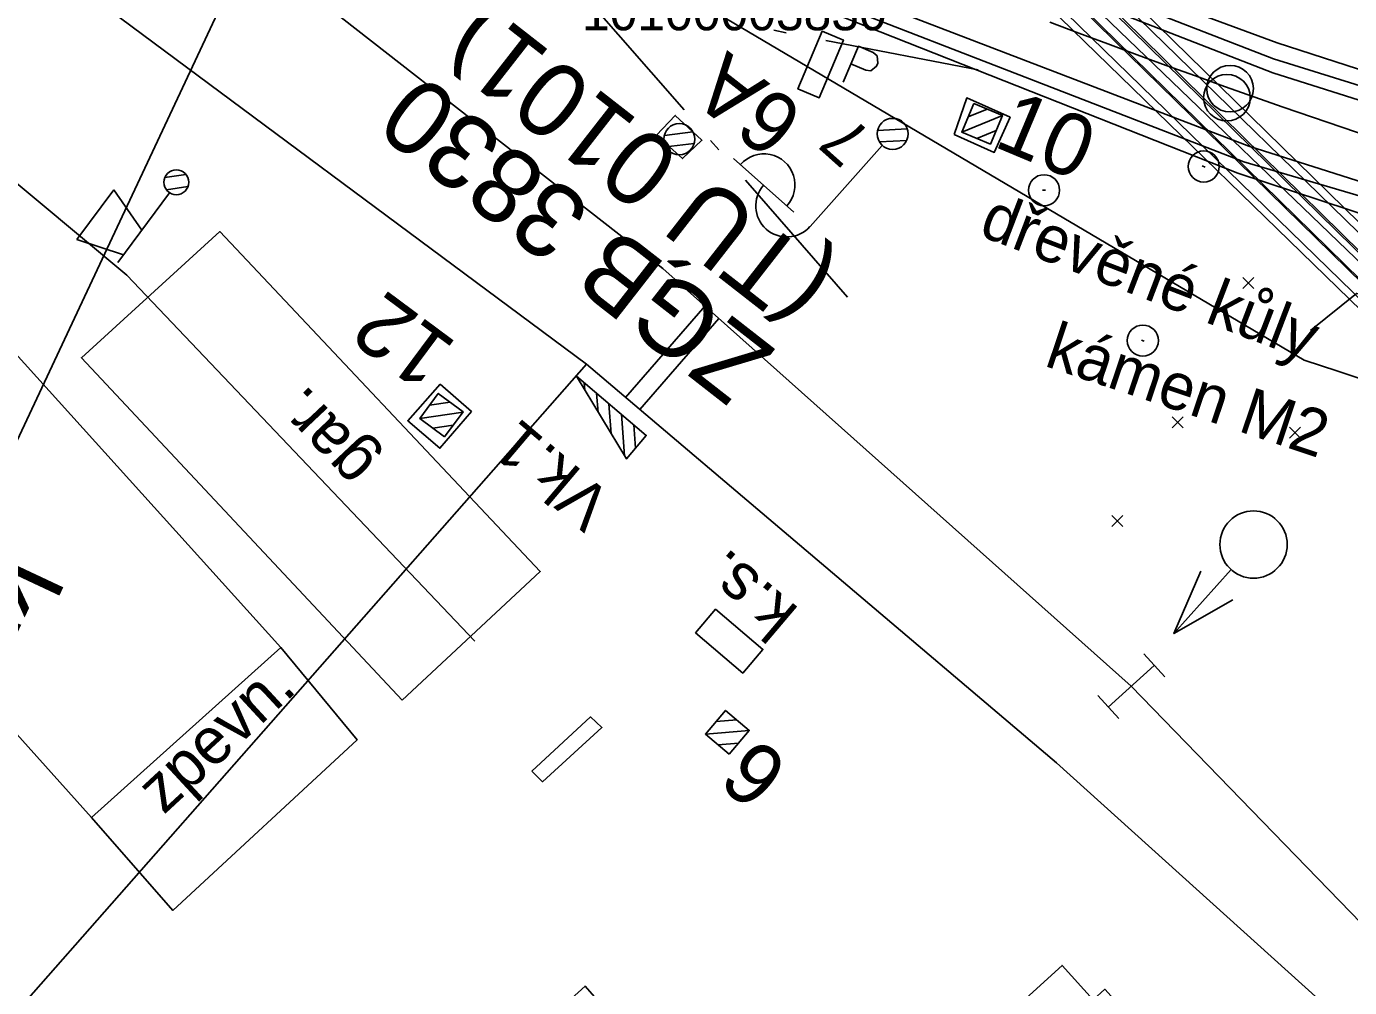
# Model space of a CAD drawing. Extents: x -800194 to -799078, y -1007177 to -1006597.
# Drawn here: x -799787.92 to -799745.3, y -1007007.87 to -1006976.93 of the extents above; entities that cross this region are included whole.
import ezdxf

# ---------------------------------------------------------------- set-up
doc = ezdxf.new("R2010")
doc.units = 0
for name, color, linetype in [('02_Osa_koleje', 7, 'Continuous'), ('_návrh', 7, 'Continuous'), ('_Vrstva 7 - Přesunutá', 7, 'Continuous'), ('Vrstva 1', 7, 'Continuous'), ('Vrstva 11', 7, 'Continuous'), ('Vrstva 12', 7, 'Continuous'), ('Vrstva 16', 7, 'Continuous'), ('Vrstva 17', 7, 'Continuous'), ('Vrstva 18', 7, 'Continuous'), ('Vrstva 23', 7, 'Continuous'), ('Vrstva 25', 7, 'Continuous'), ('Vrstva 3', 7, 'Continuous'), ('Vrstva 33', 7, 'Continuous'), ('Vrstva 36', 7, 'Continuous'), ('Vrstva 4', 7, 'Continuous'), ('Vrstva 49', 7, 'Continuous'), ('Vrstva 5', 7, 'Continuous'), ('Vrstva 50', 7, 'Continuous'), ('Vrstva 55', 7, 'Continuous'), ('Vrstva 60', 7, 'Continuous'), ('Vrstva 63', 7, 'Continuous'), ('Vrstva 7', 7, 'Continuous')]:
    doc.layers.add(name, color=color, linetype=linetype)

msp = doc.modelspace()

# ---------------------------------------------------------------- linework, layer by layer
at = {"layer": '02_Osa_koleje'}
msp.add_lwpolyline([(-799754.96, -1006976.789), (-799754.025, -1006977.142), (-799753.088, -1006977.491), (-799752.149, -1006977.838), (-799751.21, -1006978.181), (-799750.27, -1006978.521), (-799749.328, -1006978.858), (-799748.386, -1006979.192), (-799747.442, -1006979.523), (-799746.497, -1006979.85), (-799745.551, -1006980.175), (-799744.604, -1006980.496)], dxfattribs=at)
at = {"layer": '_návrh'}
for points in [[(-799821.595, -1006948.007), (-799811.064, -1006954.324), (-799803.753, -1006958.707), (-799793.935, -1006964.581), (-799784.224, -1006971.671), (-799782.913, -1006972.63), (-799767.418, -1006984.719), (-799752.333, -1006998.173), (-799735.027, -1007015.997), (-799721.623, -1007030.81), (-799713.555, -1007039.726), (-799713.111, -1007040.218)], [(-799820.755, -1006954.001), (-799803.004, -1006964.743), (-799786.682, -1006975.322), (-799769.882, -1006987.807), (-799754.745, -1007000.643), (-799736.311, -1007017.261), (-799721.623, -1007030.81)]]:
    msp.add_lwpolyline(points, dxfattribs=at)
at = {"layer": '_Vrstva 7 - Přesunutá'}
msp.add_circle((-799749.152, -1006978.93), 0.75, dxfattribs=at)
at = {"layer": 'Vrstva 1'}
msp.add_lwpolyline([(-799773.482, -1006996.72), (-799784.684, -1006984.939), (-799796.383, -1006975.181), (-799798.809, -1006973.435), (-799814.345, -1006963.355), (-799826.008, -1006956.394)], dxfattribs=at)
at = {"layer": 'Vrstva 11'}
for p, q in [((-799757.587, -1006979.838), (-799756.976, -1006979.588)), ((-799757.792, -1006980.327), (-799756.487, -1006979.793)), ((-799766.454, -1006980.322), (-799767.374, -1006980.435)), ((-799757.307, -1006980.534), (-799756.688, -1006980.28)), ((-799766.415, -1006980.695), (-799767.322, -1006980.806)), ((-799774.277, -1006989.026), (-799774.939, -1006989.123)), ((-799773.856, -1006989.342), (-799775.251, -1006989.548)), ((-799774.172, -1006989.768), (-799774.826, -1006989.864)), ((-799765.042, -1006999.255), (-799765.709, -1006999.31)), ((-799764.642, -1006999.598), (-799766.047, -1006999.714)), ((-799764.985, -1007000.003), (-799765.643, -1007000.057))]:
    msp.add_line(p, q, dxfattribs=at)
for points in [[(-799757.407, -1006979.408), (-799756.485, -1006979.794), (-799756.871, -1006980.716), (-799757.793, -1006980.33)], [(-799774.451, -1006990.143), (-799775.254, -1006989.546), (-799774.657, -1006988.743), (-799773.854, -1006989.34)], [(-799765.287, -1007000.359), (-799766.05, -1006999.712), (-799765.403, -1006998.949), (-799764.64, -1006999.596)]]:
    msp.add_lwpolyline(points, close=True, dxfattribs=at)
msp.add_circle((-799766.892, -1006980.556), 0.5, dxfattribs=at)
at = {"layer": 'Vrstva 12'}
for points in [[(-799758.044, -1006980.409), (-799757.635, -1006979.231), (-799756.238, -1006979.849), (-799756.747, -1006980.984), (-799758.044, -1006980.409)], [(-799767.624, -1006980.428), (-799767.025, -1006979.792), (-799766.166, -1006980.593), (-799766.788, -1006981.184), (-799767.624, -1006980.428)], [(-799774.6, -1006988.448), (-799773.586, -1006989.331), (-799774.604, -1006990.51), (-799775.637, -1006989.625), (-799774.6, -1006988.448)]]:
    msp.add_lwpolyline(points, dxfattribs=at)
at = {"layer": 'Vrstva 16'}
for points in [[(-799783.708, -1006948.669), (-799779.9, -1006952.065), (-799777.252, -1006954.333), (-799763.672, -1006965.935), (-799754.476, -1006974.829), (-799742.393, -1006986.703), (-799736.524, -1006991.578), (-799726.778, -1006999.642)], [(-799726.857, -1006999.659), (-799736.574, -1006991.623), (-799742.439, -1006986.725), (-799754.518, -1006974.879), (-799763.734, -1006965.993), (-799777.293, -1006954.374), (-799779.945, -1006952.099), (-799783.722, -1006948.693)], [(-799784.356, -1006949.5), (-799780.347, -1006952.62), (-799777.716, -1006954.827), (-799764.168, -1006966.436), (-799754.935, -1006975.363), (-799742.857, -1006987.188), (-799736.94, -1006992.081), (-799727.324, -1007000.028)], [(-799727.258, -1006999.988), (-799736.887, -1006992.032), (-799742.859, -1006987.132), (-799754.894, -1006975.337), (-799764.135, -1006966.374), (-799777.698, -1006954.783), (-799780.331, -1006952.581), (-799784.321, -1006949.462)], [(-799779.465, -1006951.506), (-799778.251, -1006952.583), (-799776.738, -1006953.884), (-799763.224, -1006965.504), (-799753.999, -1006974.421), (-799741.964, -1006986.204), (-799736.168, -1006991.012), (-799728.577, -1006997.215), (-799726.123, -1006999.163)], [(-799727.952, -1007000.326), (-799729.82, -1006998.717), (-799737.37, -1006992.486), (-799743.358, -1006987.594), (-799755.401, -1006975.883), (-799764.592, -1006966.926), (-799778.073, -1006955.449), (-799779.598, -1006954.142), (-799780.843, -1006953.125)], [(-799785.824, -1007002.398), (-799779.728, -1006996.929), (-799777.27, -1006999.897), (-799783.203, -1007005.389), (-799785.824, -1007002.398)]]:
    msp.add_lwpolyline(points, dxfattribs=at)
at = {"layer": 'Vrstva 17'}
for points in [[(-799746.564, -1006986.717), (-799745.074, -1006985.521), (-799738.458, -1006986.883), (-799728.745, -1006990.03), (-799724.988, -1006990.685)], [(-799776.389, -1007013.671), (-799769.929, -1007007.827), (-799768.722, -1007009.2), (-799767.356, -1007008.223), (-799755.62, -1007020.402)]]:
    msp.add_lwpolyline(points, dxfattribs=at)
at = {"layer": 'Vrstva 18'}
for points in [[(-799776.738, -1006953.884), (-799763.224, -1006965.504), (-799753.999, -1006974.421), (-799741.964, -1006986.204), (-799736.168, -1006991.012)], [(-799728.689, -1006997.417), (-799736.272, -1006991.186), (-799742.111, -1006986.385), (-799754.178, -1006974.631), (-799763.368, -1006965.72), (-799777.061, -1006954.31)], [(-799736.701, -1006991.694), (-799742.573, -1006986.82), (-799754.68, -1006975.182), (-799763.887, -1006966.256), (-799777.391, -1006954.732)], [(-799737.37, -1006992.486), (-799743.358, -1006987.594), (-799755.401, -1006975.883), (-799764.592, -1006966.926), (-799778.073, -1006955.449)], [(-799729.664, -1006998.596), (-799737.245, -1006992.341), (-799743.186, -1006987.438), (-799755.222, -1006975.72), (-799764.444, -1006966.802), (-799777.959, -1006955.323)]]:
    msp.add_lwpolyline(points, dxfattribs=at)
at = {"layer": 'Vrstva 23'}
for points in [[(-799795.856, -1006979.079), (-799779.728, -1006996.929), (-799785.824, -1007002.398), (-799801.87, -1006984.513), (-799795.856, -1006979.079)], [(-799775.824, -1006998.626), (-799786.148, -1006987.593), (-799781.696, -1006983.534), (-799771.373, -1006994.479), (-799775.824, -1006998.626)], [(-799771.638, -1007000.908), (-799769.754, -1006999.159), (-799769.387, -1006999.5), (-799771.3, -1007001.249), (-799771.638, -1007000.908)], [(-799756.701, -1007031.945), (-799748.818, -1007024.882), (-799742.835, -1007031.56), (-799739.203, -1007028.306), (-799738.261, -1007029.357), (-799736.112, -1007027.467), (-799737.076, -1007026.37), (-799736.711, -1007026.049), (-799742.825, -1007019.446), (-799742.529, -1007019.177), (-799746.942, -1007014.309), (-799747.197, -1007014.54), (-799753.188, -1007007.931), (-799753.56, -1007008.268), (-799754.56, -1007007.163), (-799756.669, -1007009.071), (-799755.683, -1007010.172), (-799759.339, -1007013.448), (-799754.227, -1007019.154), (-799755.62, -1007020.402), (-799754.738, -1007021.386), (-799761.075, -1007027.063), (-799756.701, -1007031.945)]]:
    msp.add_lwpolyline(points, dxfattribs=at)
at = {"layer": 'Vrstva 25'}
for p, q in [((-799759.551, -1006980.219), (-799760.507, -1006980.274)), ((-799759.566, -1006980.595), (-799760.444, -1006980.645)), ((-799760.353, -1006980.759), (-799762.682, -1006983.371)), ((-799763.205, -1006982.905), (-799765.145, -1006981.175))]:
    msp.add_line(p, q, dxfattribs=at)
msp.add_lwpolyline([(-799766.372, -1006996.457), (-799765.725, -1006995.694), (-799764.2, -1006996.987), (-799764.847, -1006997.75), (-799766.372, -1006996.457)], dxfattribs=at)
msp.add_circle((-799760.02, -1006980.386), 0.5, dxfattribs=at)
for centre, start, end in [((-799764.167, -1006982.031), 317.5683, 138.9735), ((-799763.429, -1006982.706), 138.2709, 318.2709)]:
    msp.add_arc(centre, 1, start, end, dxfattribs=at)
at = {"layer": 'Vrstva 3'}
for p, q in [((-799769.882, -1006987.807), (-799828.64, -1007054.5)), ((-799769.958, -1006988.398), (-799769.933, -1006988.638)), ((-799769.558, -1006988.737), (-799769.507, -1006989.353)), ((-799769.157, -1006989.077), (-799769.085, -1006990.046)), ((-799768.757, -1006989.417), (-799768.653, -1006990.755)), ((-799768.357, -1006989.756), (-799768.307, -1006990.509)), ((-799767.963, -1006990.09), (-799767.967, -1006990.109)), ((-799750.958, -1006996.476), (-799749.12, -1006994.416)), ((-799751.927, -1006997.131), (-799751.256, -1006997.873)), ((-799751.592, -1006997.502), (-799753.074, -1006998.844)), ((-799753.41, -1006998.473), (-799752.739, -1006999.215))]:
    msp.add_line(p, q, dxfattribs=at)
for points in [[(-799770.205, -1006988.188), (-799768.596, -1006990.85), (-799767.956, -1006990.096), (-799770.205, -1006988.188)], [(-799750.095, -1006994.472), (-799750.958, -1006996.476), (-799749.065, -1006995.39)]]:
    msp.add_lwpolyline(points, dxfattribs=at)
msp.add_circle((-799748.396, -1006993.609), 1.084, dxfattribs=at)
at = {"layer": 'Vrstva 33'}
for p, q in [((-799782.786, -1006981.691), (-799783.46, -1006981.79)), ((-799786.302, -1006983.792), (-799785.109, -1006982.186)), ((-799785.109, -1006982.186), (-799784.203, -1006983.482)), ((-799784.978, -1006984.526), (-799783.313, -1006982.28)), ((-799782.719, -1006982.086), (-799783.408, -1006982.187)), ((-799784.8, -1006984.285), (-799786.302, -1006983.792))]:
    msp.add_line(p, q, dxfattribs=at)
msp.add_circle((-799783.093, -1006981.945), 0.401, dxfattribs=at)
at = {"layer": 'Vrstva 36'}
msp.add_lwpolyline([(-799762.294, -1006977.079), (-799761.607, -1006977.367), (-799762.386, -1006979.225), (-799763.073, -1006978.937)], close=True, dxfattribs=at)
msp.add_lwpolyline([(-799761.609, -1006978.721), (-799761.124, -1006977.564), (-799760.643, -1006977.766), (-799760.518, -1006977.875), (-799760.494, -1006978.105), (-799760.537, -1006978.207), (-799760.719, -1006978.356), (-799760.882, -1006978.337), (-799761.363, -1006978.135)], dxfattribs=at)
at = {"layer": 'Vrstva 4'}
for points in [[(-799766.319, -1006970.565), (-799760.949, -1006972.542), (-799747.638, -1006977.46), (-799730.549, -1006982.982), (-799710.066, -1006987.578), (-799704.728, -1006988.346), (-799693.001, -1006990.373), (-799682.434, -1006991.64), (-799671.27, -1006992.619), (-799659.31, -1006993.026), (-799648.69, -1006993.125), (-799637.398, -1006992.704), (-799625.913, -1006992.175), (-799614.965, -1006990.831), (-799603.911, -1006989.312), (-799592.728, -1006987.172), (-799581.605, -1006984.547), (-799570.583, -1006981.598), (-799559.909, -1006978.216), (-799542.956, -1006972.25), (-799531.79, -1006967.658), (-799521.285, -1006962.191), (-799511.236, -1006957.129)], [(-799779.678, -1006964.304), (-799766.319, -1006970.565), (-799761.253, -1006973.176), (-799747.77, -1006978.421), (-799730.774, -1006983.8), (-799710.333, -1006988.709), (-799704.916, -1006989.741), (-799693.131, -1006991.407), (-799682.585, -1006992.929), (-799671.325, -1006993.879), (-799659.363, -1006994.45), (-799648.66, -1006994.501), (-799637.23, -1006994.127), (-799626.066, -1006993.335), (-799614.788, -1006992.17), (-799603.669, -1006990.506), (-799592.467, -1006988.452), (-799581.281, -1006985.916), (-799570.22, -1006982.998), (-799559.296, -1006979.606), (-799542.375, -1006973.485), (-799531.236, -1006968.774), (-799520.48, -1006963.762), (-799510.394, -1006958.536)], [(-799776.864, -1006969.085), (-799770.965, -1006971.646), (-799761.91, -1006975.649), (-799748.544, -1006980.777), (-799731.457, -1006986.215), (-799711.132, -1006991.054), (-799705.482, -1006992.16), (-799693.53, -1006994.084), (-799682.801, -1006995.384), (-799671.514, -1006996.319), (-799659.449, -1006996.851), (-799648.588, -1006996.949), (-799637.262, -1006996.573), (-799625.835, -1006995.773), (-799614.546, -1006994.586), (-799603.199, -1006992.945), (-799591.969, -1006990.857), (-799580.647, -1006988.335), (-799569.534, -1006985.311), (-799558.557, -1006981.947), (-799541.405, -1006975.739), (-799530.263, -1006971.071), (-799519.455, -1006966), (-799509.248, -1006960.724)], [(-799776.864, -1006969.085), (-799771.262, -1006971.982), (-799762.131, -1006976.093), (-799748.706, -1006981.286), (-799731.51, -1006986.353), (-799711.222, -1006991.459), (-799705.527, -1006992.587), (-799693.582, -1006994.543), (-799682.85, -1006995.904), (-799671.5, -1006996.805), (-799659.556, -1006997.356), (-799648.616, -1006997.341), (-799637.276, -1006997.071), (-799625.828, -1006996.297), (-799614.43, -1006995.109), (-799603.18, -1006993.475), (-799591.849, -1006991.264), (-799580.564, -1006988.698), (-799569.449, -1006985.746), (-799558.385, -1006982.386), (-799541.268, -1006976.227), (-799530.102, -1006971.505), (-799519.398, -1006966.36), (-799509.087, -1006961.127)], [(-799779.011, -1006963.023), (-799770.632, -1006967.944), (-799766.319, -1006970.565), (-799761.021, -1006972.82), (-799747.748, -1006977.966), (-799730.719, -1006983.271), (-799710.195, -1006988.108), (-799704.765, -1006989.181), (-799693.072, -1006990.965), (-799682.554, -1006992.238), (-799671.266, -1006993.222), (-799659.388, -1006993.765), (-799648.658, -1006993.824), (-799637.385, -1006993.531), (-799625.769, -1006992.728), (-799614.9, -1006991.542), (-799603.91, -1006989.963), (-799592.572, -1006987.892), (-799581.421, -1006985.419), (-799570.327, -1006982.332), (-799559.429, -1006979.066), (-799542.601, -1006973.013), (-799531.454, -1006968.25), (-799520.744, -1006963.214)], [(-799776.864, -1006969.085), (-799771.693, -1006972.522), (-799762.217, -1006976.394), (-799748.898, -1006981.647), (-799733.68, -1006986.66), (-799728.795, -1006987.945), (-799711.349, -1006992.599), (-799705.744, -1006994.116), (-799693.689, -1006996.09), (-799689.347, -1006996.226), (-799688.222, -1006996.296), (-799683.105, -1006997.407), (-799671.667, -1006998.275)]]:
    msp.add_lwpolyline(points, dxfattribs=at)
at = {"layer": 'Vrstva 49'}
for p, q in [((-799748.745, -1006985.013), (-799748.391, -1006985.367)), ((-799748.745, -1006985.367), (-799748.391, -1006985.013)), ((-799751.015, -1006989.494), (-799750.661, -1006989.848)), ((-799751.015, -1006989.848), (-799750.661, -1006989.494)), ((-799747.241, -1006989.831), (-799746.887, -1006990.185)), ((-799747.241, -1006990.185), (-799746.887, -1006989.831)), ((-799752.956, -1006992.672), (-799752.602, -1006993.026)), ((-799752.956, -1006993.026), (-799752.602, -1006992.672))]:
    msp.add_line(p, q, dxfattribs=at)
at = {"layer": 'Vrstva 5'}
msp.add_line((-799796.24, -1007007.322), (-799778.659, -1006969.886), dxfattribs=at)
at = {"layer": 'Vrstva 50'}
for p, q in [((-799755.194, -1006982.202), (-799755.094, -1006982.202)), ((-799752.008, -1006987.026), (-799751.914, -1006987.06))]:
    msp.add_line(p, q, dxfattribs=at)
for centre in [(-799755.144, -1006982.202), (-799751.961, -1006987.043)]:
    msp.add_circle(centre, 0.5, dxfattribs=at)
at = {"layer": 'Vrstva 55'}
msp.add_lwpolyline([(-799785.23, -1006937.71), (-799791.69, -1006959.99), (-799791.97, -1006960.97), (-799746.76, -1006987.67), (-799745.68, -1006988.03), (-799733.28, -1006992.13)], dxfattribs=at)
at = {"layer": 'Vrstva 63'}
for p, q in [((-799770.028, -1006975.851), (-799766.738, -1006979.616)), ((-799763.843, -1006977.052), (-799763.451, -1006977.128)), ((-799762.175, -1006977.376), (-799757.266, -1006978.329)), ((-799765.883, -1006980.595), (-799765.62, -1006980.896)), ((-799764.764, -1006981.875), (-799761.474, -1006985.641))]:
    msp.add_line(p, q, dxfattribs=at)
at = {"layer": 'Vrstva 7'}
for p, q in [((-799750.046, -1006981.42), (-799749.952, -1006981.454)), ((-799768.626, -1006988.872), (-799766.064, -1006985.927)), ((-799768.168, -1006989.26), (-799765.616, -1006986.326)), ((-799767.02, -1006987.483), (-799767.02, -1006987.483))]:
    msp.add_line(p, q, dxfattribs=at)
for centre, radius in [((-799749.254, -1006979.22), 0.75), ((-799749.999, -1006981.437), 0.5)]:
    msp.add_circle(centre, radius, dxfattribs=at)

# ---------------------------------------------------------------- texts
at = {"layer": 'Vrstva 11'}
for s, rotation, p in [('6A', 142.0391, (-799762.78, -1006979.693)), ('10', 337.2647, (-799756.815, -1006980.771)), ('12', 143.3819, (-799773.999, -1006987.156)), ('6', 139.7024, (-799763.268, -1007000.735))]:
    msp.add_text(s, height=2, rotation=rotation, dxfattribs=at).set_placement(p)
at = {"layer": 'Vrstva 16'}
msp.add_text('zpevn.', height=1.5, rotation=42.7895, dxfattribs=at).set_placement((-799783.502, -1007002.329))
at = {"layer": 'Vrstva 23'}
msp.add_text('gar.', height=1.5, rotation=133.3248, dxfattribs=at).set_placement((-799776.592, -1006990.935))
at = {"layer": 'Vrstva 25'}
for s, rotation, p in [('7', 138.2709, (-799760.637, -1006980.425)), ('k.s.', 139.7024, (-799762.993, -1006995.696))]:
    msp.add_text(s, height=1.5, rotation=rotation, dxfattribs=at).set_placement(p)
at = {"layer": 'Vrstva 3'}
msp.add_text('Vk.1', height=1.5, rotation=139.7024, dxfattribs=at).set_placement((-799768.972, -1006992.12))
at = {"layer": 'Vrstva 5'}
msp.add_text('km 204,169', height=2.5, rotation=244.8436, dxfattribs=at).set_placement((-799789.022, -1006993.664))
at = {"layer": 'Vrstva 50'}
for s, rotation, p in [('dřevěné kůly', 339.0461, (-799757.288, -1006983.641)), ('kámen M2', 341.4135, (-799755.173, -1006987.846))]:
    msp.add_text(s, height=1.5, rotation=rotation, dxfattribs=at).set_placement(p)
at = {"layer": 'Vrstva 60'}
msp.add_text('10100003830', height=1.2, dxfattribs=at).set_placement((-799770.028, -1006977.051))
at = {"layer": 'Vrstva 63'}
for s, p in [('(TÚ 0101)', (-799761.816, -1006984.928)), ('ZGB 3830', (-799763.727, -1006987.377))]:
    msp.add_text(s, height=2.4, rotation=142.0391, dxfattribs=at).set_placement(p)

doc.saveas('drawing.dxf')
